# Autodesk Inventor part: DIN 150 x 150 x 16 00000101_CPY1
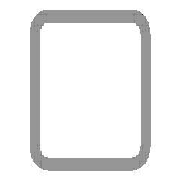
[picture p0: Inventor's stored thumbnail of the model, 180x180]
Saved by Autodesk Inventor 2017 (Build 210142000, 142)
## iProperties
Created: 2017-11
Part Number: DIN 150 x 150 x 16 00000101_CPY1
Material: Steel, Mild
Description: Cold formed welded structural hollow sections of non-alloy and fine grain structural steel
Document SubType Name: Modeling
Standard: DIN
Designer: iusti
Standard Revision: 2006-07
Standards Organization: DIN
Language: en-US
Size Designation: 150 x 150 x 16
Categories: <MemberInstance><Categories><Category DisplayName="Structural Shapes" InternalName="089c4875-fa83-4c05-b084-43b9cc11f5ed" Mnemonic="GRDR"><CategoryParameter Dis
Stock Number: 150 x 150 x 16
Mass: 88044.5 g
Surface Area: 14205.2 cm^2
Volume: 11215.9 cm^3
Density: 7.85 g/cm^3
Appearance: Semi-Polished
IsCustomPart: 1
G_W: 150.000 mm
G_H: 150.000 mm
G_L: 1602.478 mm
+987C6673-447C-412A-9B24-0CD20188E66E+CUTDETAIL2: Miter 69.88 deg
+D0655DDE-97F9-4B99-A490-E36C02108510+CUTDETAIL3: Miter 45.00 deg
_CCFamilyMember: 76
_CCFamilyDisplayName: DIN EN 10219-2 (Square Hollow Section - Cold Formed) - Cold formed welded structural hollow sections of non-alloy and fine grain structural steel
_FrameMemberDoc: Frame Member File
_Version: 15.0.0
_GetPNFromCC: 1
Author: iusti
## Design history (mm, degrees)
node "Start plane"
node "End plane"
sketch "Sketch"
  geometry: L1 (-75, -27)-(-75, 27); L2 (-27, 75)-(27, 75); L3 (75, 27)-(75, -27); L4 (27, -75)-(-27, -75); L5 (-27, 59)-(27, 59); L6 (59, 27)-(59, -27); L7 (27, -59)-(-27, -59); L8 (-59, -27)-(-59, 27); L9 (0, 118.918)-(0, -118.918) reference; L10 (-118.918, 0)-(118.918, 0) reference; A1 r 48 centre (-27, -27) between (-75, -27) and (-27, -75); A2 r 48 centre (-27, 27) between (-27, 75) and (-75, 27); A3 r 48 centre (27, 27) between (75, 27) and (27, 75); A4 r 48 centre (27, -27) between (27, -75) and (75, -27); A5 r 32 centre (-27, 27) between (-27, 59) and (-59, 27); A6 r 32 centre (27, 27) between (59, 27) and (27, 59); A7 r 32 centre (27, -27) between (27, -59) and (59, -27); A8 r 32 centre (-27, -27) between (-59, -27) and (-27, -59)
  constraints: 16 end point, 16 point on circle, 8 centre point, 8 tangent, 4 parallel, 3 equal radius, 2 perpendicular, 7 other
  dimensions: "d7" = 48 radius of A1 (= G_IR); "d10" = 150 distance between parallel lines of L2 L4 (= G_H); "d11" = 150 distance between parallel lines of L1 L3 (= G_W); "d12" = 16 distance between parallel lines of L3 L6 (= G_T); "d15" = 75 distance between parallel lines of L2 L10 (= 0.5 x d10); "d16" = 75 distance between parallel lines of L9 L3 (= 0.5 x d11)
extrude "Body" new body sketch "Sketch" stored distance "d3" = 1602.4779 (= G_L); taper "d4" = 0 deg
node "Driven Length"
  sketch "Sketch3"
    geometry: L1 (0, 0)-(10, 0) reference
    constraints: 2 end point, 1 horizontal
  workplane "Work Plane3"
  sketch "Sketch4"
    geometry: L1 (-2, -27.478)-(12, -27.478) reference; L2 (-2, 1575)-(12, 1575) reference
    dimensions: "d18" = 1602.4779 distance between parallel lines of L1 L2 (derived)
workplane "Work Plane5"
split "Split2"
workplane "Work Plane6"
split "Split3"
body "Solid1"
other parameters: "G_W" = 150 [user parameter; used in 1 equation term], "G_H" = 150 [user parameter; used in 1 equation term], "G_T" = 16 [user parameter; used in 1 equation term], "G_IR" = 48 [user parameter; used in 1 equation term], "G_L" = 1602.4779 (= d18) [user parameter; used in 1 equation term], "G_OFFSET_START" = 27.4779 [user parameter; used in 1 equation term], "G_OFFSET_END" = 75 [user parameter; used in 1 equation term], "d13" = -27.4779 (= -G_OFFSET_START), "d14" = 1575 (= G_OFFSET_END + B_L), "d17" = 90 deg
